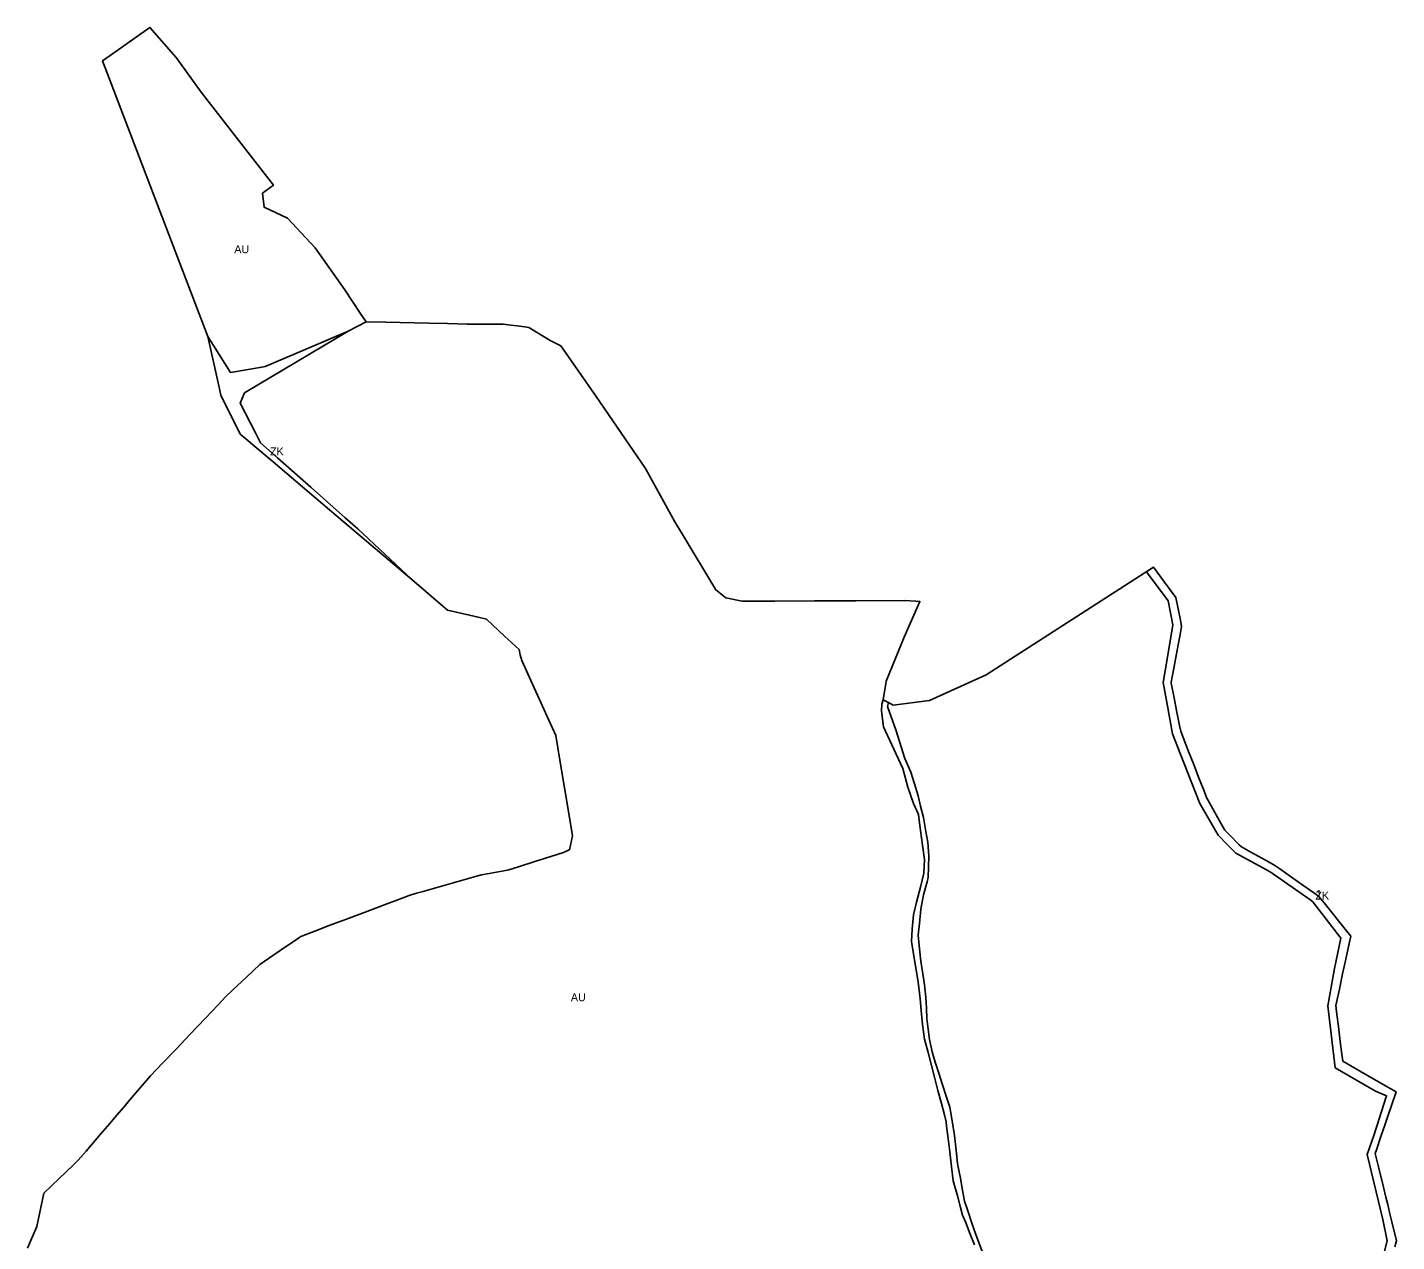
# Model space of a CAD drawing. Extents: x -537068 to -534056, y -1176840 to -1172401.
# Drawn here: x -536659 to -535803, y -1173160 to -1172401 of the extents above; entities that cross this region are included whole.
import ezdxf

# ---------------------------------------------------------------- set-up
doc = ezdxf.new("R2010")
doc.units = 0
for name, color, linetype in [('90710013', 7, 'Continuous'), ('90710023', 7, 'Continuous'), ('90750013', 7, 'Continuous'), ('ID_navrh', 7, 'Continuous')]:
    doc.layers.add(name, color=color, linetype=linetype)

msp = doc.modelspace()

# ---------------------------------------------------------------- linework, layer by layer
at = {"layer": '90710013'}
msp.add_lwpolyline([(-536458.7, -1172590.95), (-536523.55, -1172629.55), (-536526.3, -1172636), (-536516.66, -1172654.49), (-536513.4, -1172660.75), (-536502.91, -1172670.05), (-536481.9, -1172688.67), (-536460.52, -1172707.62), (-536452.7, -1172714.55), (-536418.9, -1172746.3), (-536462.09, -1172709.68), (-536484.27, -1172690.86), (-536505.63, -1172672.75), (-536516.95, -1172663.15), (-536522.73, -1172658.22), (-536526.15, -1172655.3), (-536538.2, -1172631.05), (-536539.49, -1172625.24), (-536546.35, -1172594.35), (-536532.3, -1172616.75), (-536512.71, -1172613.46), (-536510.55, -1172613.1), (-536491.5, -1172604.96), (-536468.48, -1172595.13)], close=True, dxfattribs=at)
at = {"layer": '90710023'}
for points in [[(-535815.41, -1173183.23), (-535809.4, -1173159.72), (-535811.98, -1173146.28), (-535821.78, -1173105.71), (-535817.53, -1173093.06), (-535809.74, -1173068.93), (-535816.55, -1173065.96), (-535841.82, -1173051.44), (-535846.5, -1173012.72), (-535842.26, -1172989.48), (-535838.29, -1172970.5), (-535855.91, -1172947.65), (-535857.64, -1172946.32), (-535882.46, -1172928.97), (-535904.02, -1172917.3), (-535909.21, -1172912.08), (-535914.98, -1172906.07), (-535926.35, -1172886.22), (-535936.35, -1172860.76), (-535943.5, -1172842.76), (-535946.82, -1172824.1), (-535949.37, -1172810.58), (-535946.83, -1172796.06), (-535943.26, -1172774.58), (-535946.25, -1172759.46), (-535959.84, -1172741.48), (-535955.36, -1172738.54), (-535948.47, -1172747.96), (-535941.46, -1172757.54), (-535940.03, -1172764.61), (-535938.61, -1172771.63), (-535937.81, -1172775.58), (-535938.75, -1172780.67), (-535940.53, -1172790.29), (-535942.42, -1172800.49), (-535944.26, -1172810.47), (-535944.35, -1172810.96), (-535942.53, -1172820.14), (-535940.96, -1172828.06), (-535939.1, -1172837.45), (-535938.4, -1172840.99), (-535936.86, -1172844.94), (-535933.42, -1172853.74), (-535930.24, -1172861.87), (-535927.19, -1172869.67), (-535924.42, -1172876.77), (-535922.01, -1172882.93), (-535921.42, -1172883.99), (-535917.24, -1172891.45), (-535913.07, -1172898.88), (-535910.86, -1172902.83), (-535907.97, -1172905.74), (-535901.77, -1172912), (-535900.49, -1172913.29), (-535894.48, -1172916.63), (-535885.06, -1172921.85), (-535880.22, -1172924.54), (-535876.49, -1172927.14), (-535869.12, -1172932.28), (-535862.03, -1172937.24), (-535854.63, -1172942.41), (-535852.25, -1172944.07), (-535848.79, -1172948.41), (-535843.81, -1172954.66), (-535838.95, -1172960.69), (-535833.92, -1172966.93), (-535832.16, -1172969.11), (-535833.17, -1172973.85), (-535835.24, -1172983.57), (-535837.17, -1172992.62), (-535839.24, -1173002.35), (-535840.99, -1173010.54), (-535841.42, -1173012.58), (-535840.74, -1173018.1), (-535839.8, -1173025.68), (-535838.65, -1173034.94), (-535837.65, -1173043.02), (-535837.12, -1173047.25), (-535832.06, -1173050.18), (-535821.69, -1173056.18), (-535810.31, -1173062.76), (-535803.75, -1173066.56), (-535806.87, -1173075.7), (-535808.51, -1173080.5), (-535810.81, -1173087.24), (-535813.27, -1173094.44), (-535816.11, -1173102.75), (-535816.85, -1173104.93), (-535814.58, -1173114.19), (-535811.65, -1173126.13), (-535810.12, -1173132.36), (-535808.98, -1173137), (-535807.59, -1173142.68), (-535806.37, -1173147.65), (-535803.45, -1173159.52), (-535804.66, -1173163.34)], [(-536067.25, -1173162.07), (-536069.87, -1173155.47), (-536072.96, -1173147.68), (-536074.66, -1173143.51), (-536075.94, -1173138.86), (-536077.98, -1173131.44), (-536080.56, -1173122.07), (-536081.61, -1173113.41), (-536082.76, -1173103.9), (-536083.77, -1173095.58), (-536084.71, -1173087.87), (-536085.04, -1173085.17), (-536086.1, -1173080.94), (-536087.96, -1173073.84), (-536090.11, -1173065.63), (-536092.08, -1173058.13), (-536094.2, -1173050.05), (-536096.3, -1173041.85), (-536098.43, -1173033.51), (-536099.85, -1173024.39), (-536100.63, -1173015.7), (-536101.29, -1173008.44), (-536102.56, -1172997.62), (-536103.71, -1172990.44), (-536105.35, -1172980.27), (-536106.61, -1172972.41), (-536106.17, -1172964.82), (-536105.42, -1172955.83), (-536103.42, -1172947.87), (-536101.08, -1172938.51), (-536098.87, -1172929.69), (-536098.52, -1172921.31), (-536099.69, -1172912.19), (-536100.91, -1172903.06), (-536101.98, -1172895), (-536102.22, -1172893.17), (-536105.33, -1172886.18), (-536108.97, -1172876.06), (-536112.15, -1172864.37), (-536118.96, -1172849.66), (-536124.19, -1172838.36), (-536125.3, -1172828.45), (-536125.21, -1172824.08), (-536124.44, -1172821.34), (-536121.11, -1172823.11), (-536121.71, -1172825.68), (-536116.12, -1172840.78), (-536110.83, -1172858.02), (-536107.14, -1172866.56), (-536104.67, -1172873.88), (-536102.5, -1172881.47), (-536100.92, -1172887.9), (-536099.14, -1172895.05), (-536097.78, -1172903.68), (-536096.5, -1172910.48), (-536095.77, -1172918.93), (-536095.97, -1172926.09), (-536096.22, -1172932.35), (-536096.83, -1172935.16), (-536099.04, -1172943.29), (-536100.78, -1172952.25), (-536101.59, -1172961.15), (-536102.37, -1172968.61), (-536101.69, -1172977.15), (-536100.82, -1172984.8), (-536099.62, -1172992.76), (-536098.41, -1172999.67), (-536097.61, -1173007.49), (-536097.35, -1173014.21), (-536097.05, -1173020.73), (-536096.29, -1173027.29), (-536095.42, -1173033.76), (-536093.72, -1173041.46), (-536091.76, -1173048), (-536089.64, -1173054.8), (-536087.22, -1173062.12), (-536084.89, -1173069.1), (-536082.69, -1173076.04), (-536081.27, -1173084.59), (-536079.75, -1173093.78), (-536078.81, -1173102.85), (-536077.91, -1173111.51), (-536076.05, -1173120.42), (-536074.89, -1173126.99), (-536073.61, -1173134.74), (-536071.52, -1173140.85), (-536068.75, -1173149.14), (-536065.55, -1173157.97), (-536062.1, -1173167.32)]]:
    msp.add_lwpolyline(points, dxfattribs=at)
at = {"layer": '90750013'}
msp.add_lwpolyline([(-536447.56, -1172585.12), (-536458.7, -1172590.95), (-536468.48, -1172595.13), (-536491.5, -1172604.96), (-536510.55, -1172613.1), (-536512.71, -1172613.46), (-536532.3, -1172616.75), (-536546.35, -1172594.35), (-536570.75, -1172530.47), (-536612.18, -1172421.97), (-536609.44, -1172420.03), (-536600.44, -1172413.66), (-536591.78, -1172407.53), (-536582.63, -1172401.06), (-536566.18, -1172419.82), (-536550.54, -1172441.5), (-536505.34, -1172499.69), (-536512.26, -1172504.73), (-536511.24, -1172513.54), (-536496.58, -1172520.33), (-536479.35, -1172538.8), (-536460.88, -1172565.06), (-536451.15, -1172579.71)], close=True, dxfattribs=at)
for points in [[(-536659.19, -1173164.25), (-536653.2, -1173150.64), (-536648.99, -1173129.84), (-536639.32, -1173120.63), (-536635.08, -1173116.59), (-536630.21, -1173111.96), (-536627.4, -1173109.28), (-536622.46, -1173103.5), (-536613.5, -1173093.03), (-536607.72, -1173086.27), (-536603.46, -1173081.29), (-536598.91, -1173075.96), (-536595.1, -1173071.5), (-536591.33, -1173067.1), (-536582.33, -1173056.57), (-536574.95, -1173048.81), (-536566.09, -1173039.49), (-536557.62, -1173030.58), (-536547.89, -1173020.35), (-536540.04, -1173012.1), (-536535.09, -1173006.89), (-536530.99, -1173003.01), (-536522.21, -1172994.7), (-536513.96, -1172986.9), (-536505.26, -1172980.93), (-536497.15, -1172975.36), (-536492.55, -1172972.2), (-536488.89, -1172969.69), (-536488.3, -1172969.28), (-536479.52, -1172965.97), (-536469.49, -1172962.18), (-536459.78, -1172958.52), (-536449.79, -1172954.75), (-536439.24, -1172950.76), (-536433.89, -1172948.74), (-536429.36, -1172947.03), (-536420.63, -1172943.74), (-536419.87, -1172943.45), (-536416.04, -1172942.37), (-536411.9, -1172941.2), (-536408.3, -1172940.19), (-536400.91, -1172938.1), (-536390.82, -1172935.25), (-536385.03, -1172933.62), (-536379.05, -1172931.93), (-536375.4, -1172930.9), (-536370.65, -1172930.03), (-536361.51, -1172928.35), (-536358.36, -1172927.77), (-536352.31, -1172925.85), (-536341.37, -1172922.38), (-536336.06, -1172920.69), (-536331.35, -1172919.2), (-536324.23, -1172916.94), (-536320.98, -1172915.41), (-536320.39, -1172915.13), (-536318.6, -1172906.51), (-536322.14, -1172885.03), (-536324.96, -1172867.92), (-536327.66, -1172851.52), (-536328.95, -1172843.7), (-536333.29, -1172834.16), (-536343.55, -1172811.61), (-536350.25, -1172796.9), (-536351.12, -1172793.25), (-536351.9, -1172790), (-536360.9, -1172781.58), (-536372.15, -1172771.05), (-536377.53, -1172769.83), (-536382.88, -1172768.6), (-536396.7, -1172765.45), (-536418.9, -1172746.3), (-536452.7, -1172714.55), (-536460.52, -1172707.62), (-536481.9, -1172688.67), (-536502.91, -1172670.05), (-536513.4, -1172660.75), (-536516.66, -1172654.49), (-536526.3, -1172636), (-536523.55, -1172629.55), (-536458.7, -1172590.95), (-536447.56, -1172585.12), (-536435.22, -1172585.39), (-536408.24, -1172585.98), (-536396.61, -1172586.24), (-536384.28, -1172586.51), (-536372.53, -1172586.5), (-536361.86, -1172586.49), (-536348.38, -1172588.23), (-536345.78, -1172588.57), (-536332.55, -1172596.81), (-536325.88, -1172600.09), (-536303.65, -1172631.89), (-536272.95, -1172676.8), (-536254.51, -1172710.25), (-536250, -1172717.59), (-536228.97, -1172752.63), (-536222.62, -1172757.59), (-536212.45, -1172759.79), (-536191.95, -1172759.7), (-536167.19, -1172759.6), (-536141.53, -1172759.49), (-536111.2, -1172759.36), (-536103.89, -1172759.78), (-536101.41, -1172759.97), (-536111.3, -1172782.28), (-536122.4, -1172809.77), (-536122.64, -1172811.14), (-536124.44, -1172821.34), (-536125.21, -1172824.08), (-536125.3, -1172828.45), (-536124.19, -1172838.36), (-536118.96, -1172849.66), (-536112.15, -1172864.37), (-536108.97, -1172876.06), (-536105.33, -1172886.18), (-536102.22, -1172893.17), (-536101.98, -1172895), (-536100.91, -1172903.06), (-536099.69, -1172912.19), (-536098.52, -1172921.31), (-536098.87, -1172929.69), (-536101.08, -1172938.51), (-536103.42, -1172947.87), (-536105.42, -1172955.83), (-536106.17, -1172964.82), (-536106.61, -1172972.41), (-536105.35, -1172980.27), (-536103.71, -1172990.44), (-536102.56, -1172997.62), (-536101.29, -1173008.44), (-536100.63, -1173015.7), (-536099.85, -1173024.39), (-536098.43, -1173033.51), (-536096.3, -1173041.85), (-536094.2, -1173050.05), (-536092.08, -1173058.13), (-536090.11, -1173065.63), (-536087.96, -1173073.84), (-536086.1, -1173080.94), (-536085.04, -1173085.17), (-536084.71, -1173087.87), (-536083.77, -1173095.58), (-536082.76, -1173103.9), (-536081.61, -1173113.41), (-536080.56, -1173122.07), (-536077.98, -1173131.44), (-536075.94, -1173138.86), (-536074.66, -1173143.51), (-536072.96, -1173147.68), (-536069.87, -1173155.47), (-536067.25, -1173162.07)], [(-536062.1, -1173167.32), (-536065.55, -1173157.97), (-536068.75, -1173149.14), (-536071.52, -1173140.85), (-536073.61, -1173134.74), (-536074.89, -1173126.99), (-536076.05, -1173120.42), (-536077.91, -1173111.51), (-536078.81, -1173102.85), (-536079.75, -1173093.78), (-536081.27, -1173084.59), (-536082.69, -1173076.04), (-536084.89, -1173069.1), (-536087.22, -1173062.12), (-536089.64, -1173054.8), (-536091.76, -1173048), (-536093.72, -1173041.46), (-536095.42, -1173033.76), (-536096.29, -1173027.29), (-536097.05, -1173020.73), (-536097.35, -1173014.21), (-536097.61, -1173007.49), (-536098.41, -1172999.67), (-536099.62, -1172992.76), (-536100.82, -1172984.8), (-536101.69, -1172977.15), (-536102.37, -1172968.61), (-536101.59, -1172961.15), (-536100.78, -1172952.25), (-536099.04, -1172943.29), (-536096.83, -1172935.16), (-536096.22, -1172932.35), (-536095.97, -1172926.09), (-536095.77, -1172918.93), (-536096.5, -1172910.48), (-536097.78, -1172903.68), (-536099.14, -1172895.05), (-536100.92, -1172887.9), (-536102.5, -1172881.47), (-536104.67, -1172873.88), (-536107.14, -1172866.56), (-536110.83, -1172858.02), (-536116.12, -1172840.78), (-536121.71, -1172825.68), (-536121.11, -1172823.11), (-536118.1, -1172824.71), (-536095.31, -1172821.88), (-536059.93, -1172805.73), (-535955.36, -1172738.54), (-535959.84, -1172741.48), (-535946.25, -1172759.46), (-535943.26, -1172774.58), (-535946.83, -1172796.06), (-535949.37, -1172810.58), (-535946.82, -1172824.1), (-535943.5, -1172842.76), (-535936.35, -1172860.76), (-535926.35, -1172886.22), (-535914.98, -1172906.07), (-535909.21, -1172912.08), (-535904.02, -1172917.3), (-535882.46, -1172928.97), (-535857.64, -1172946.32), (-535855.91, -1172947.65), (-535838.29, -1172970.5), (-535842.26, -1172989.48), (-535846.5, -1173012.72), (-535841.82, -1173051.44), (-535816.55, -1173065.96), (-535809.74, -1173068.93), (-535817.53, -1173093.06), (-535821.78, -1173105.71), (-535811.98, -1173146.28), (-535809.4, -1173159.72), (-535815.41, -1173183.23)]]:
    msp.add_lwpolyline(points, dxfattribs=at)

# ---------------------------------------------------------------- texts
at = {"layer": '90710013'}
msp.add_text('ZK', height=5, rotation=0, dxfattribs=at).set_placement((-536507.51, -1172668.63))
at = {"layer": '90710023'}
msp.add_text('ZK', height=5, rotation=0, dxfattribs=at).set_placement((-535854.21, -1172946.28))
at = {"layer": '90750013'}
for rotation, p in [(0, (-536529.87, -1172542.23)), (360, (-536319.52, -1173009.82))]:
    msp.add_text('AU', height=5, rotation=rotation, dxfattribs=at).set_placement(p)
at = {"layer": 'ID_navrh'}
msp.add_text('1', height=6, rotation=360, dxfattribs=at).set_placement((-535854.21, -1172946.28))

doc.saveas('drawing.dxf')
